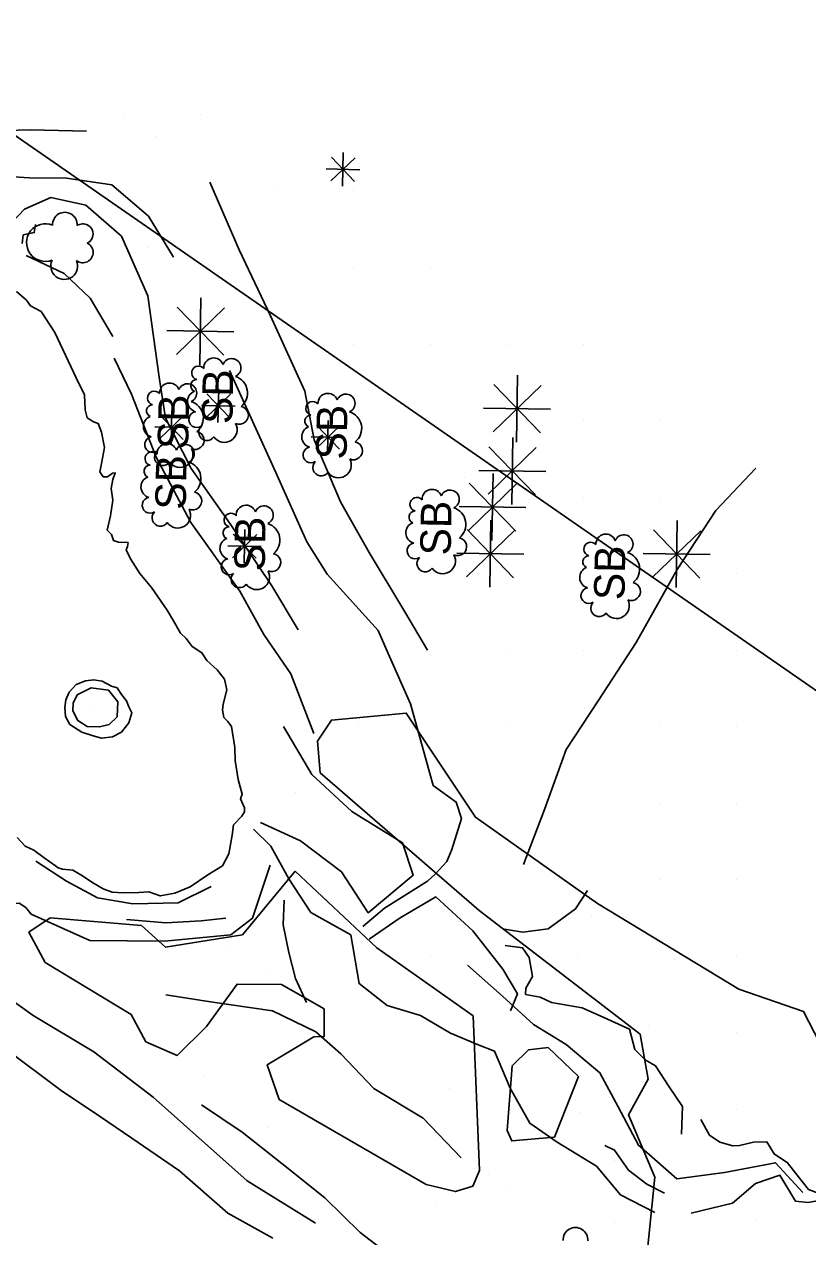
# Model space of a CAD drawing. Extents: x 19528164 to 19545171, y 7585743 to 7602745.
# Drawn here: x 19531898.9 to 19532103.7, y 7590371.8 to 7590688.6 of the extents above; entities that cross this region are included whole.
import ezdxf

# ---------------------------------------------------------------- set-up
doc = ezdxf.new("R2010")
doc.units = 0
for name, color, linetype in [('Default', 7, 'Continuous'), ('PhoBreakLine', 7, 'Continuous'), ('PhoEdgeWater', 7, 'Continuous'), ('PhoISAEPoints', 7, 'Continuous'), ('PhoSurveyLimits', 7, 'Continuous'), ('PhoVegetation', 7, 'Continuous')]:
    doc.layers.add(name, color=color, linetype=linetype)

# ---------------------------------------------------------------- blocks, each defined once
blk = doc.blocks.new('SHRUB')
at = {"layer": 'Default'}
for centre, radius, start, end in [((-5.57, 5.14), 2.08, 10.5948, 214.3611), ((-0.81, 4.83), 2.81, 22.6036, 165.7836), ((3.27, 5.33), 1.59, 0.4605, 158.7839), ((6.61, 4.92), 1.8, 311.3936, 166.4114), ((-8.82, 2.41), 2.18, 45.3455, 236.8073), ((8, 0.98), 2.6, 290.9039, 94.3687), ((-8.06, -2.12), 3.34, 125.8289, 299.2848), ((8.09, -3.71), 2.42, 204.8294, 69.8871), ((-4.25, -5.95), 2.36, 157.0258, 349.7602), ((1.54, -3.45), 4.54, 220.0183, 343.6977)]:
    blk.add_arc(centre, radius, start, end, dxfattribs=at)
blk.add_text('SB', height=7.998, dxfattribs=at).set_placement((-6.62, -4.17))

msp = doc.modelspace()

# ---------------------------------------------------------------- linework, layer by layer
at = {"layer": 'PhoBreakLine'}
for points in [[(19531782.05, 7590545.48), (19531786.14, 7590562.63), (19531790.68, 7590579.04), (19531797.33, 7590596.74), (19531806.19, 7590614.43), (19531815.93, 7590629.27), (19531826.1, 7590639.25), (19531839.67, 7590647.99), (19531850.52, 7590653.84), (19531862.46, 7590657.93), (19531880.77, 7590660.49), (19531900.46, 7590660.93), (19531915.15, 7590660.58)], [(19531865.98, 7590647.15), (19531881.05, 7590649.67), (19531900.28, 7590648.45), (19531909.92, 7590648.33), (19531921.75, 7590646.61), (19531931.35, 7590638.4), (19531937.87, 7590627.71)], [(19531947.35, 7590647.32), (19531955.05, 7590629.66), (19531963.26, 7590612.33), (19531972.23, 7590592.69), (19531974.62, 7590579.97), (19531981.54, 7590563.74), (19531989.01, 7590550.55), (19531998.33, 7590535.04), (19532004.29, 7590525.06)], [(19531810.72, 7590591.39), (19531818.3, 7590602.67), (19531824.24, 7590613.67), (19531836.9, 7590626.74), (19531848.48, 7590635.43), (19531862.98, 7590641.76), (19531873.11, 7590644.48), (19531876.88, 7590644.47), (19531879.97, 7590641.92), (19531889.89, 7590637.29), (19531893.5, 7590635.63), (19531895.79, 7590636.93), (19531898.92, 7590640.27), (19531905.79, 7590643.28), (19531914.94, 7590641.32), (19531924.25, 7590633.22), (19531931.21, 7590617.56), (19531934.15, 7590596.36), (19531935.81, 7590585.65), (19531942.46, 7590572.48), (19531952.68, 7590558.04), (19531963.61, 7590541.87), (19531970.49, 7590530.34)], [(19531898.33, 7590631.26), (19531898.62, 7590633.51), (19531901.46, 7590634.14), (19531901.79, 7590636.26)], [(19531899.4, 7590628.15), (19531909.31, 7590623.45), (19531916.1, 7590616.98), (19531922.02, 7590606.99)], [(19531922.38, 7590601.27), (19531926.88, 7590591.94), (19531933.39, 7590575.43), (19531942.37, 7590558.34), (19531955.22, 7590540.45), (19531961.47, 7590529.1), (19531968.58, 7590518.8), (19531974.6, 7590503.21)], [(19531952.53, 7590598.07), (19531964.61, 7590571.45), (19531972.75, 7590553.31), (19531978.01, 7590544.9), (19531991.35, 7590530.19), (19531994.03, 7590524.19), (19531999.85, 7590511.02), (19532005.72, 7590489.7), (19532011.78, 7590485.31), (19532013.14, 7590481), (19532010.65, 7590472.91), (19532009.35, 7590469.83), (19532006.24, 7590466.46), (19532004.3, 7590464.68)], [(19532029.37, 7590468.98), (19532034.86, 7590483.42), (19532040.56, 7590499.09), (19532048.92, 7590511.76), (19532058.78, 7590527.04), (19532069.58, 7590546.13), (19532079.61, 7590561.48), (19532090.12, 7590572.54)], [(19531733.12, 7590543.67), (19531751.89, 7590527.49), (19531762.44, 7590520.85), (19531774.75, 7590513.35), (19531794.09, 7590499.89), (19531808.16, 7590491.09), (19531823.07, 7590479.33), (19531836.66, 7590466.91), (19531855.06, 7590450.46), (19531871.88, 7590438.53), (19531883.44, 7590427.87), (19531893.59, 7590421.11), (19531908.51, 7590409.93), (19531918.55, 7590403.29), (19531926.97, 7590397.55), (19531939.48, 7590388.95), (19531952.11, 7590377.89), (19531963.88, 7590371.42)], [(19531780.48, 7590519.39), (19531795.96, 7590508.65), (19531812.85, 7590498.48), (19531830.68, 7590484.97), (19531847.73, 7590470.83), (19531862.72, 7590458.58), (19531880.48, 7590444.35), (19531901.16, 7590429.56), (19531917.06, 7590420.11), (19531932.58, 7590408.19), (19531957.17, 7590386.39), (19531975.03, 7590375.33)], [(19531960.64, 7590479.98), (19531971.05, 7590475.21), (19531981.82, 7590467.09), (19531988.81, 7590456.42), (19532000.5, 7590466.22), (19531997.76, 7590474.68), (19531984.49, 7590482.88), (19531974.06, 7590492.57), (19531966.67, 7590505.08)], [(19531958.75, 7590478.23), (19531963.32, 7590473.82), (19531968.03, 7590465.29), (19531973.81, 7590456.47), (19531984.2, 7590450.63), (19531986.39, 7590437.91), (19531993.76, 7590432.22), (19532002.44, 7590429.53), (19532010.28, 7590424.96), (19532017.36, 7590421.96), (19532021.8, 7590420.22), (19532025.86, 7590410.6), (19532030.99, 7590401.43), (19532038.2, 7590396.49), (19532048.46, 7590390.18), (19532054.73, 7590382.72), (19532063.68, 7590378.11)], [(19531901.91, 7590469.91), (19531909.92, 7590464.7), (19531918.02, 7590460.34), (19531927.26, 7590458.74), (19531939.06, 7590459.03), (19531947.74, 7590463.28)], [(19531916.03, 7590449.2), (19531935.57, 7590448.99), (19531952.87, 7590450.6), (19531958.53, 7590454.97), (19531963.11, 7590468.84)], [(19531987.41, 7590452.82), (19531993.06, 7590457.65), (19532004.3, 7590464.68)], [(19531989.01, 7590449.5), (19531997.13, 7590455.07), (19532006.49, 7590460.54), (19532016.16, 7590451.69), (19532024, 7590441.64), (19532027.82, 7590435.26), (19532026.01, 7590430.82)], [(19532024.37, 7590452.13), (19532029.2, 7590451.36), (19532035.84, 7590452.22), (19532042.99, 7590457.41), (19532046.13, 7590462.2)], [(19531892.51, 7590456.06), (19531895.24, 7590458.82), (19531897.55, 7590458.9), (19531899.26, 7590457.79), (19531900.64, 7590456.05), (19531916.03, 7590449.2)], [(19531966.84, 7590459.67), (19531966.59, 7590453.21), (19531968, 7590446.02), (19531969.77, 7590439.24), (19531972.66, 7590432.99)], [(19531925.56, 7590454.62), (19531935.9, 7590453.78), (19531945.15, 7590454.27), (19531951.56, 7590454.98)], [(19532070.7, 7590398.55), (19532070.89, 7590405.8), (19532067.49, 7590410.92), (19532063.87, 7590416.44), (19532061.18, 7590417.98), (19532058.44, 7590420.72), (19532057.11, 7590426.03), (19532050.33, 7590429.03), (19532044.69, 7590431.53), (19532036.7, 7590432.99), (19532033.77, 7590434.33), (19532029.92, 7590435.06), (19532029.97, 7590436.74), (19532031.71, 7590439.73), (19532030.89, 7590444.69), (19532029.12, 7590447.26), (19532024.59, 7590447.86)], [(19532069.45, 7590386.86), (19532059.42, 7590395.65), (19532054.11, 7590405.66), (19532049.34, 7590414.62), (19532040.51, 7590421.98), (19532031.96, 7590427.22), (19532023.87, 7590434.64), (19532014.75, 7590442.73)], [(19531935.92, 7590434.98), (19531947.57, 7590433.16), (19531963.74, 7590430.79), (19531975.1, 7590425.26), (19531981.63, 7590419.58), (19531990.28, 7590410.47), (19532003.11, 7590402.72), (19532013.1, 7590392.4)], [(19531996.03, 7590365.75), (19531986.71, 7590372.87), (19531977.4, 7590381.95), (19531966.22, 7590390.86), (19531955.81, 7590399.05), (19531945.2, 7590406.25)], [(19532073.24, 7590377.95), (19532084.01, 7590380.5), (19532089.98, 7590385.67), (19532096.4, 7590387.86), (19532100.48, 7590381.03), (19532103.68, 7590380.73), (19532108.2, 7590381.47), (19532106.39, 7590383.1), (19532103.89, 7590384.14), (19532100.95, 7590387.81), (19532098.38, 7590391.08), (19532094.91, 7590393.39), (19532092.96, 7590396.58), (19532089.53, 7590396.5), (19532085.81, 7590395.6), (19532084.05, 7590395.55), (19532080.66, 7590396.48), (19532077.97, 7590398.32), (19532075.71, 7590402.42)], [(19532050.66, 7590395.59), (19532053.18, 7590394.38), (19532056.82, 7590389.17), (19532061.58, 7590385.46), (19532066.2, 7590383.18)], [(19532069.45, 7590386.86), (19532081.88, 7590388.54), (19532095.22, 7590391.08), (19532102.35, 7590383.28)]]:
    msp.add_lwpolyline(points, dxfattribs=at)
msp.add_lwpolyline([(19531912.71, 7590513.33), (19531916.37, 7590515.21), (19531920.91, 7590514.58), (19531923.34, 7590511.49), (19531923.15, 7590507.61), (19531921.03, 7590505.59), (19531918.54, 7590504.98), (19531915.35, 7590505.11), (19531912.87, 7590506.61), (19531911.61, 7590509.2), (19531911.69, 7590511.19)], close=True, dxfattribs=at)
at = {"layer": 'PhoEdgeWater'}
msp.add_lwpolyline([(19531896.8, 7590618.71), (19531899.46, 7590616.45), (19531900.5, 7590615.01), (19531903.25, 7590613.51), (19531906.88, 7590607.99), (19531908.99, 7590603.58), (19531912.48, 7590596.14), (19531914.6, 7590591.76), (19531914.83, 7590587.79), (19531915.34, 7590585.75), (19531916.99, 7590584.71), (19531918.23, 7590584.23), (19531919.06, 7590581.96), (19531919.84, 7590578), (19531919.07, 7590573.83), (19531918.64, 7590571.57), (19531919.51, 7590570.35), (19531920.64, 7590570.27), (19531921.94, 7590571.3), (19531922.67, 7590571.33), (19531922, 7590569.62), (19531921.59, 7590567.22), (19531922.05, 7590564.17), (19531921.44, 7590560.15), (19531920.57, 7590556.36), (19531921.64, 7590555.22), (19531922.2, 7590553.67), (19531923.52, 7590553.2), (19531926.01, 7590553.14), (19531925.82, 7590552.08), (19531925.51, 7590551.22), (19531926.67, 7590548.88), (19531929.1, 7590545.07), (19531932.14, 7590541.38), (19531936.2, 7590535.44), (19531937.92, 7590532.67), (19531939.75, 7590529.49), (19531941.16, 7590528.06), (19531942.79, 7590525.96), (19531945.32, 7590524.34), (19531946.59, 7590522.36), (19531949.26, 7590519.92), (19531951.21, 7590517.41), (19531951.82, 7590514.66), (19531950.9, 7590510.88), (19531950.71, 7590509.36), (19531951, 7590507.46), (19531952.1, 7590506.41), (19531953.02, 7590505.05), (19531953.93, 7590499.59), (19531953.96, 7590496.17), (19531954.77, 7590491.26), (19531955.81, 7590487.41), (19531955.41, 7590486.16), (19531956.41, 7590483.82), (19531956.43, 7590482.77), (19531955.74, 7590481.67), (19531953.56, 7590479.36), (19531953.23, 7590476.65), (19531952.35, 7590471.84), (19531950.67, 7590468.68), (19531946.84, 7590466.3), (19531942.24, 7590463.16), (19531938.27, 7590461.53), (19531934.41, 7590460.82), (19531931.47, 7590461.91), (19531928.84, 7590461.66), (19531924.69, 7590461.64), (19531921.84, 7590461.8), (19531919.48, 7590462.68), (19531916.93, 7590464.14), (19531913.69, 7590466.29), (19531911.57, 7590467.51), (19531908.87, 7590467.78), (19531907.73, 7590468.11), (19531907.01, 7590468.68), (19531904.09, 7590470.75), (19531901.38, 7590472.78), (19531899.09, 7590473.77), (19531897, 7590476.08)], dxfattribs=at)
msp.add_lwpolyline([(19531910.6, 7590514.05), (19531912.48, 7590516.04), (19531914.86, 7590517.04), (19531917.06, 7590517.23), (19531919.27, 7590516.88), (19531921.64, 7590515.61), (19531923.13, 7590515.22), (19531924.28, 7590513.46), (19531925.61, 7590511.78), (19531926.23, 7590510.17), (19531926.99, 7590508.61), (19531926.21, 7590506.04), (19531924.33, 7590503.62), (19531921.91, 7590502.34), (19531919.08, 7590502.03), (19531916.84, 7590502.62), (19531913.94, 7590503.56), (19531910.74, 7590505.62), (19531909.66, 7590507.73), (19531909.45, 7590510.06), (19531909.73, 7590512.06)], close=True, dxfattribs=at)
at = {"layer": 'PhoISAEPoints'}
for p, q in [((19531925, 7590665), (19531925, 7590665)), ((19531945, 7590665), (19531945, 7590665)), ((19531933.23, 7590659.14), (19531933.23, 7590659.14)), ((19531965, 7590645), (19531965, 7590645)), ((19531985, 7590645), (19531985, 7590645)), ((19531931.06, 7590630.23), (19531931.06, 7590630.23)), ((19531945, 7590625), (19531945, 7590625)), ((19531985, 7590625), (19531985, 7590625)), ((19532005, 7590625), (19532005, 7590625)), ((19531985, 7590605), (19531985, 7590605)), ((19532005, 7590605), (19532005, 7590605)), ((19532025, 7590605), (19532025, 7590605)), ((19532045, 7590605), (19532045, 7590605)), ((19531948.11, 7590598.07), (19531948.11, 7590598.07)), ((19531985, 7590585), (19531985, 7590585)), ((19532005, 7590585), (19532005, 7590585)), ((19532025, 7590585), (19532025, 7590585)), ((19532045, 7590585), (19532045, 7590585)), ((19532065, 7590585), (19532065, 7590585)), ((19532013.82, 7590570.04), (19532013.82, 7590570.04)), ((19532005, 7590565), (19532005, 7590565)), ((19532045, 7590565), (19532045, 7590565)), ((19532065, 7590565), (19532065, 7590565)), ((19532005, 7590545), (19532005, 7590545)), ((19532025, 7590545), (19532025, 7590545)), ((19532045, 7590545), (19532045, 7590545)), ((19532085, 7590545), (19532085, 7590545)), ((19532025, 7590525), (19532025, 7590525)), ((19532045, 7590525), (19532045, 7590525)), ((19532085, 7590525), (19532085, 7590525)), ((19531916.29, 7590509.63), (19531916.29, 7590509.63)), ((19531986.19, 7590506.17), (19531986.19, 7590506.17)), ((19532025, 7590505), (19532025, 7590505)), ((19532065, 7590505), (19532065, 7590505)), ((19532085, 7590505), (19532085, 7590505)), ((19531969.89, 7590487.89), (19531969.89, 7590487.89)), ((19532065, 7590485), (19532065, 7590485)), ((19532085, 7590485), (19532085, 7590485)), ((19531903.55, 7590465.57), (19531903.55, 7590465.57)), ((19532065, 7590465), (19532065, 7590465)), ((19532085, 7590465), (19532085, 7590465)), ((19532047.27, 7590455.74), (19532047.27, 7590455.74)), ((19531952.63, 7590447.34), (19531952.63, 7590447.34)), ((19532005, 7590445), (19532005, 7590445)), ((19532043.41, 7590445.55), (19532043.41, 7590445.55)), ((19532068.86, 7590444.31), (19532068.86, 7590444.31)), ((19532085, 7590445), (19532085, 7590445)), ((19531912.57, 7590439.72), (19531912.57, 7590439.72)), ((19531962.13, 7590440.97), (19531962.13, 7590440.97)), ((19531929.84, 7590426.07), (19531929.84, 7590426.07)), ((19532062.14, 7590427.05), (19532062.14, 7590427.05)), ((19532085, 7590425), (19532085, 7590425)), ((19531946.04, 7590413.7), (19531946.04, 7590413.7)), ((19532010.13, 7590410.49), (19532010.13, 7590410.49)), ((19532044.35, 7590404.15), (19532044.35, 7590404.15)), ((19532085, 7590405), (19532085, 7590405)), ((19531962.4, 7590400.28), (19531962.4, 7590400.28)), ((19531988.75, 7590393.14), (19531988.75, 7590393.14)), ((19532053.25, 7590391.79), (19532053.25, 7590391.79)), ((19532020.18, 7590388.03), (19532020.18, 7590388.03)), ((19532025, 7590385), (19532025, 7590385)), ((19532006.75, 7590380.93), (19532006.75, 7590380.93)), ((19532053.23, 7590375.42), (19532053.23, 7590375.42)), ((19532090.21, 7590375.97), (19532090.21, 7590375.97))]:
    msp.add_line(p, q, dxfattribs=at)
at = {"layer": 'PhoSurveyLimits'}
msp.add_lwpolyline([(19531492.52, 7590939.32), (19532163.83, 7590474.32), (19532286.15, 7590546.02), (19532286.15, 7590546.02), (19532279.02, 7591748.83), (19532392.75, 7591747.67), (19532933.44, 7591193.6), (19533437.31, 7591046.07), (19533734.35, 7591292.49), (19534091.1, 7591487.7), (19534567.67, 7591635.69)], dxfattribs=at)
at = {"layer": 'PhoVegetation'}
for p, q in [((19531985.34, 7590653.68), (19531979.01, 7590647.64)), ((19531985.2, 7590647.49), (19531979.15, 7590653.82)), ((19531982.07, 7590646.28), (19531982.27, 7590655.03)), ((19531986.55, 7590650.56), (19531977.8, 7590650.76)), ((19531982.17, 7590650.66), (19531982.17, 7590650.66)), ((19531944.78, 7590599.61), (19531945.06, 7590617.1)), ((19531951.2, 7590614.44), (19531938.64, 7590602.27)), ((19531951.01, 7590602.08), (19531938.83, 7590614.64)), ((19531953.66, 7590608.22), (19531936.17, 7590608.5)), ((19531944.92, 7590608.36), (19531944.92, 7590608.36)), ((19532027.56, 7590579.37), (19532027.83, 7590596.86)), ((19531949.51, 7590584.49), (19531949.71, 7590593.24)), ((19532033.98, 7590594.2), (19532021.41, 7590582.03)), ((19532033.78, 7590581.84), (19532021.61, 7590594.4)), ((19531952.77, 7590591.89), (19531946.44, 7590585.85)), ((19531952.63, 7590585.7), (19531946.59, 7590592.03)), ((19531937.28, 7590578.89), (19531937.48, 7590587.64)), ((19531953.98, 7590588.77), (19531945.23, 7590588.97)), ((19531949.61, 7590588.87), (19531949.61, 7590588.87)), ((19532036.44, 7590587.98), (19532018.95, 7590588.25)), ((19532027.7, 7590588.12), (19532027.7, 7590588.12)), ((19531940.55, 7590586.29), (19531934.22, 7590580.25)), ((19531940.4, 7590580.1), (19531934.36, 7590586.43)), ((19531981.41, 7590583.69), (19531975.08, 7590577.65)), ((19531981.26, 7590577.51), (19531975.22, 7590583.83)), ((19531978.14, 7590576.3), (19531978.34, 7590585.04)), ((19531941.76, 7590583.17), (19531933.01, 7590583.37)), ((19531937.38, 7590583.27), (19531937.38, 7590583.27)), ((19531982.62, 7590580.57), (19531973.87, 7590580.77)), ((19531978.24, 7590580.67), (19531978.24, 7590580.67)), ((19532026.3, 7590563.11), (19532026.57, 7590580.6)), ((19532032.72, 7590577.94), (19532020.15, 7590565.77)), ((19532032.52, 7590565.58), (19532020.35, 7590578.14)), ((19532035.18, 7590571.72), (19532017.69, 7590571.99)), ((19532021.13, 7590553.66), (19532021.41, 7590571.15)), ((19532026.44, 7590571.86), (19532026.44, 7590571.86)), ((19532027.55, 7590568.49), (19532014.99, 7590556.32)), ((19532027.36, 7590556.13), (19532015.18, 7590568.69)), ((19532030.01, 7590562.27), (19532012.52, 7590562.55)), ((19532021.27, 7590562.41), (19532021.27, 7590562.41)), ((19532020.57, 7590541.48), (19532020.85, 7590558.97)), ((19532069.27, 7590541.41), (19532069.55, 7590558.9)), ((19531959.63, 7590555.2), (19531953.3, 7590549.16)), ((19531959.49, 7590549.02), (19531953.44, 7590555.34)), ((19531956.36, 7590547.81), (19531956.57, 7590556.55)), ((19532026.99, 7590556.31), (19532014.43, 7590544.14)), ((19532026.8, 7590543.94), (19532014.62, 7590556.51)), ((19532075.69, 7590556.24), (19532063.13, 7590544.07)), ((19532075.5, 7590543.87), (19532063.32, 7590556.44)), ((19531960.84, 7590552.08), (19531952.09, 7590552.28)), ((19531956.47, 7590552.18), (19531956.47, 7590552.18)), ((19532029.46, 7590550.09), (19532011.96, 7590550.36)), ((19532020.71, 7590550.22), (19532020.71, 7590550.22)), ((19532078.15, 7590550.02), (19532060.66, 7590550.29)), ((19532069.41, 7590550.15), (19532069.41, 7590550.15))]:
    msp.add_line(p, q, dxfattribs=at)
for points in [[(19532059.83, 7590424.68), (19532017.79, 7590457.01), (19531976.2, 7590493.01), (19531975.56, 7590501.24), (19531979.17, 7590506.77), (19531998.73, 7590508.56), (19532016.83, 7590481.37), (19532048.7, 7590458.79), (19532085.63, 7590436.48), (19532102.58, 7590430.61), (19532108.27, 7590419.45), (19532115.24, 7590421.69), (19532123.08, 7590426.21), (19532164.41, 7590417.19), (19532181.23, 7590414.7)], [(19532058.97, 7590340.79), (19532063.73, 7590387.31), (19532056.81, 7590403.64), (19532061.95, 7590412.91), (19532059.83, 7590424.68)]]:
    msp.add_lwpolyline(points, dxfattribs=at)
for points in [[(19532003.89, 7590385.43), (19531965.47, 7590407.66), (19531962.35, 7590416.64), (19531974.55, 7590423.96), (19531977.29, 7590424.12), (19531977.26, 7590431.28), (19531966.13, 7590437.68), (19531954.49, 7590437.78), (19531946.54, 7590426.65), (19531938.85, 7590419.12), (19531930.66, 7590422.68), (19531926.82, 7590429.79), (19531904.31, 7590443.44), (19531900.1, 7590451.31), (19531905.63, 7590455.11), (19531929.54, 7590453.04), (19531935.82, 7590447.45), (19531955.89, 7590450.61), (19531969.71, 7590467.27), (19531991.05, 7590447.28), (19532016.19, 7590429.45), (19532017.83, 7590389.03), (19532016.13, 7590385.01), (19532011.59, 7590383.56)], [(19532043.79, 7590413.62), (19532037.45, 7590397.79), (19532026.28, 7590396.79), (19532025.06, 7590399.52), (19532026.45, 7590416.41), (19532030.66, 7590420.57), (19532035.79, 7590421.17)]]:
    msp.add_lwpolyline(points, close=True, dxfattribs=at)
for centre, radius, start, end in [((19531909.48, 7590636.22), 3.21, 355.0943, 183.0979), ((19531904.38, 7590631.51), 4.92, 67.3012, 290.8911), ((19531914.19, 7590633.74), 2.67, 295.6203, 124.4995), ((19531914.19, 7590628.92), 2.68, 231.8463, 64.4185), ((19531909.31, 7590625.4), 3.52, 154.5785, 23.6137), ((19532042.95, 7590370.96), 3.21, 355.0943, 183.0979)]:
    msp.add_arc(centre, radius, start, end, dxfattribs=at)

# ---------------------------------------------------------------- block references
at = {"layer": 'PhoVegetation', "xscale": 0.9999999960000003, "yscale": 0.9999999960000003, "rotation": 88.89301078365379}
for p in [(19531949.22, 7590590.75), (19531937.67, 7590584.19), (19531979.06, 7590581.49), (19531937.03, 7590568.36), (19532006.28, 7590556.42), (19531957.68, 7590552.28), (19532051.72, 7590544.73)]:
    msp.add_blockref('SHRUB', p, dxfattribs=at)

doc.saveas('drawing.dxf')
